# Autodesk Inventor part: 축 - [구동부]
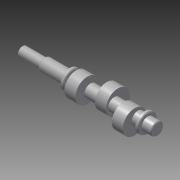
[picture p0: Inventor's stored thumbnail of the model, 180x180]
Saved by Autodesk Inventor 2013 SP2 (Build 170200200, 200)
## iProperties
Company: 한국ATC센터
Created: 2014-08
Part Number: 축 - [구동부]
Document SubType Name: Modeling
Designer: mdu
Density: 7.86 g/cm^3
Material: 강철, 연강
Mass: 516.584 g
Surface Area: 162.516 cm^2
Volume: 65.7231 cm^3
Author: mdu
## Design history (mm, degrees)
sketch "스케치1"
  geometry: L1 (-91.5, 0)-(91.5, 0); L2 (-91.5, 0)-(-91.5, 6.5); L3 (-59.681, 8.5)-(-27.5, 8.5); L4 (-27.5, 8.5)-(-27.5, 13); L5 (-27.5, 13)-(-22.5, 13); L6 (-22.5, 13)-(-22.5, 8.5); L7 (-22.5, 8.5)-(73.5, 8.5); L8 (73.5, 8.5)-(73.5, 13); L9 (73.5, 13)-(78.5, 13); L10 (78.5, 13)-(78.5, 8.5); L11 (78.5, 8.5)-(91.5, 8.5); L12 (91.5, 8.5)-(91.5, 0); L13 (-61.5, 7.45)-(-61.5, 6.5); L14 (-61.5, 6.5)-(-91.5, 6.5); L15 (-61.5, 7.45)-(-59.681, 8.5); 2 further points
  constraints: 30 end point, 6 parallel, 2 perpendicular, 1 coincident, 1 horizontal, 1 midpoint
  dimensions: "d0" = 183 distance of L1.start L1.end (derived); "d2" = 17 diameter of L3 L1; "d3" = 26 diameter of L5 L1; "d4" = 17 diameter of L7 L1; "d5" = 26 diameter of L9 L1; "d6" = 17 diameter of L11 L1; "d7" = 5 distance of L8.end L9.end; "d8" = 5 distance of L4.end L5.end; "d11" = 13 distance of L10.end L11.end; "d35" = 96 distance between parallel lines of L8 L6; "d57" = 13 diameter of L14 L1; "d58" = 64 distance between parallel lines of L4 L2; "d60" = 30 horizontal distance of L2.end L13.start; "d61" = 14.9 diameter of L13.start L1; "d62" = 30 deg angle of L3 L15
revolve "회전1" sketch "스케치1" stored, may be unused: angle "d12" = 90 deg
node "작업 평면7"
sketch "스케치6"
  geometry: C1 r 15 at (0, 5); 1 further point
  constraints: 1 centre point, 1 vertical alignment
  dimensions: "d37" = 30 diameter of C1; "d38" = 5 distance of C1.centre point (0, 0)
extrude "돌출4" join sketch "스케치6" stored distance "d33" = 15; taper "d34" = 0 deg
node "작업 평면8"
sketch "스케치7"
  geometry: L1 (0, 0)-(-6.5, -11.258); L2 (0, 0)-(13, 0); C1 r 15 at (-2.5, -4.33); A1 r 13 centre (0, 0) between (-6.5, -11.258) and (13, 0) reference; 1 further point
  constraints: 4 end point, 2 point on circle, 1 centre point, 1 horizontal, 1 point on line
  dimensions: "d40" = 120 deg angle of L1 L2; "d41" = 30 diameter of C1; "d42" = 5 distance of point (0, 0) C1.centre
extrude "돌출5" join sketch "스케치7" stored distance "d43" = 15; taper "d44" = 0 deg
node "작업 평면9"
sketch "스케치8"
  geometry: L1 (0, 0)-(4.25, -7.361); L2 (0, 0)-(-8.5, 0); C1 r 15 at (2.5, -4.33); A1 r 8.5 centre (0, 0) between (4.25, -7.361) and (-8.5, 0) reference; 1 further point
  constraints: 4 end point, 2 point on circle, 1 centre point, 1 horizontal, 1 point on line
  dimensions: "d46" = 120 deg angle of L1 L2; "d47" = 30 diameter of C1; "d48" = 5 distance of point (0, 0) C1.centre
extrude "돌출6" join sketch "스케치8" stored distance "d49" = 15; taper "d50" = 0 deg
node "작업 평면3"
sketch "스케치5"
  geometry: L1 (91.5, 6.5)-(91.5, -6.5) reference; L2 (87, -2.5)-(66, -2.5); L3 (66, 2.5)-(87, 2.5); A1 r 2.5 centre (66, 0) between (66, 2.5) and (66, -2.5); A2 r 2.5 centre (87, 0) between (87, -2.5) and (87, 2.5); 4 further points
  constraints: 4 end point, 4 point on circle, 4 tangent, 2 centre point, 2 point on line, 1 horizontal alignment, 1 midpoint, 1 parallel, 1 perpendicular
  dimensions: "d23" = 5 distance between parallel lines of L3 L2; "d36" = 28 dimension on A1 L1; "d52" = 2 distance edge to line of A2 L1
extrude "돌출3" cut sketch "스케치5" distance "d25" = 3; taper "d26" = 0 deg
chamfer "모따기1" distance "d27" = 1; stored, may be unused: second distance "d28" = 2, angle "d29" = 45 deg
fillet "모깎기1" dims "d51" = 0.3
chamfer "모따기2" distance "d53" = 1; stored, may be unused: second distance "d54" = 2, angle "d55" = 45 deg
node "작업 평면10"
fillet "모깎기2" dims "d63" = 4
fillet "모깎기3" dims "d64" = 1
node "솔리드1"
other parameters: "d39" = -32, "d45" = 32, "d66" = 6.5
